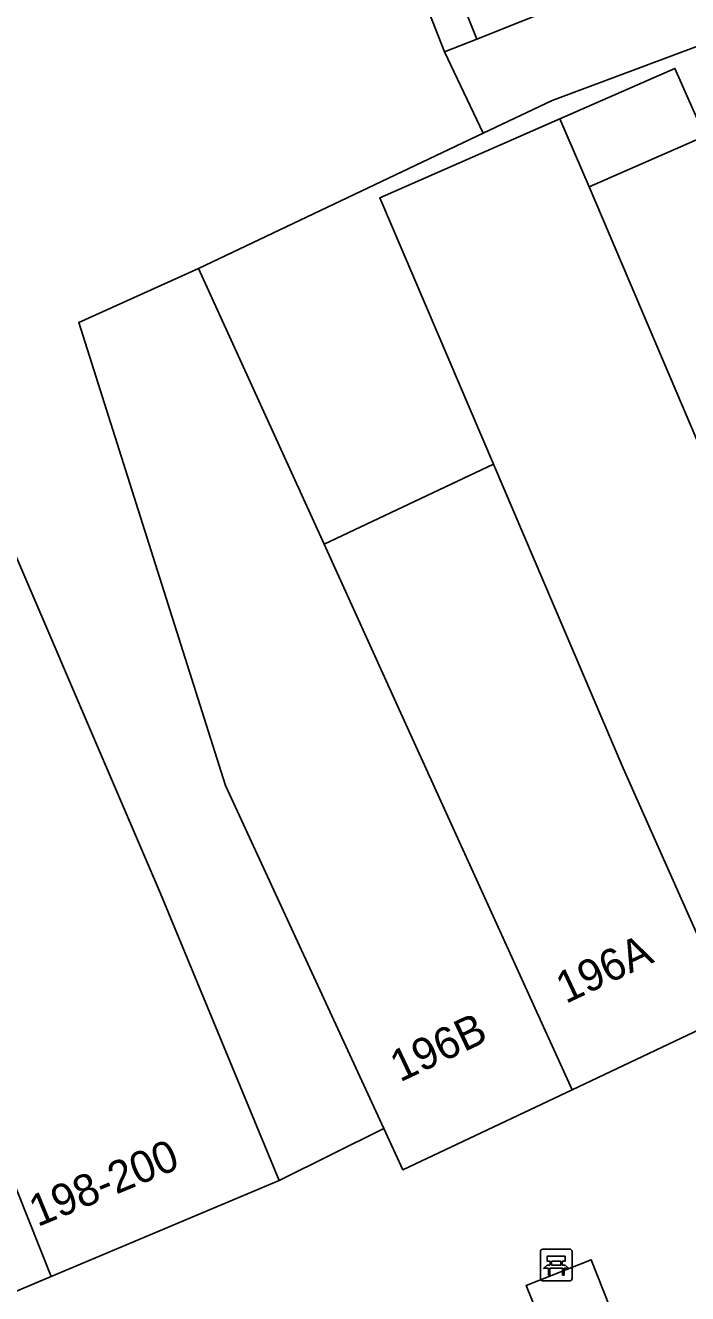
# Model space of a CAD drawing. Extents: x 159262 to 160143, y 383399 to 384319.
# Drawn here: x 159603.2 to 159624.06, y 383565.06 to 383605.01 of the extents above; entities that cross this region are included whole.
import ezdxf

# ---------------------------------------------------------------- set-up
doc = ezdxf.new("R2010")
doc.units = 0
for name, color, linetype in [('IMGEO_Bank', 7, 'Continuous'), ('IMGEO_Erf', 7, 'Continuous'), ('IMGEO_Groenvoorziening', 7, 'Continuous'), ('IMGEO_Pand', 7, 'Continuous'), ('IMGEO_Pand_nummerreeks', 7, 'Continuous'), ('IMGEO_Rijbaan_lokaal_open', 7, 'Continuous'), ('IMGEO_Voetpad_open', 7, 'Continuous')]:
    doc.layers.add(name, color=color, linetype=linetype)

msp = doc.modelspace()

# ---------------------------------------------------------------- linework, layer by layer
at = {"layer": 'IMGEO_Bank'}
for p, q in [((159619.499, 383566.463), (159620.34, 383566.463)), ((159620.34, 383566.463), (159619.499, 383566.463)), ((159619.424, 383565.538), (159619.424, 383566.379)), ((159619.424, 383566.379), (159619.424, 383565.538)), ((159619.733, 383565.969), (159619.733, 383566.075)), ((159619.777, 383566.075), (159619.777, 383565.969)), ((159620.065, 383566.081), (159619.783, 383566.081)), ((159620.071, 383565.969), (159620.071, 383566.075)), ((159620.115, 383566.075), (159620.115, 383565.969)), ((159620.424, 383566.388), (159620.424, 383565.547)), ((159620.424, 383565.547), (159620.424, 383566.388)), ((159620.121, 383565.861), (159619.728, 383565.861)), ((159619.783, 383565.963), (159620.065, 383565.963)), ((159620.349, 383565.463), (159619.508, 383565.463)), ((159619.508, 383565.463), (159620.349, 383565.463))]:
    msp.add_line(p, q, dxfattribs=at)
for points in [[(159619.727, 383566.081), (159619.641, 383566.081), (159619.641, 383566.242), (159620.204, 383566.242), (159620.204, 383566.081), (159620.121, 383566.081)], [(159619.671, 383565.861), (159619.529, 383565.861), (159619.641, 383565.963), (159619.727, 383565.963)], [(159619.721, 383565.854), (159619.721, 383565.647), (159619.678, 383565.647), (159619.678, 383565.854)], [(159620.121, 383565.963), (159620.204, 383565.963), (159620.316, 383565.861), (159620.177, 383565.861)], [(159620.171, 383565.854), (159620.171, 383565.647), (159620.127, 383565.647), (159620.127, 383565.854)]]:
    msp.add_lwpolyline(points, dxfattribs=at)
for centre, radius, start, end in [((159619.502, 383566.385), 0.0779, 92.4484, 184.2845), ((159619.502, 383566.385), 0.0779, 92.4484, 184.2845), ((159620.346, 383566.385), 0.0779, 2.4484, 94.2845), ((159620.346, 383566.385), 0.0779, 2.4484, 94.2845), ((159619.726, 383566.074), 0.00671, 2.8957, 87.1043), ((159619.783, 383566.074), 0.00671, 92.8957, 177.1043), ((159620.065, 383566.074), 0.00671, 2.8957, 87.1043), ((159620.122, 383566.074), 0.00671, 92.8957, 177.1043), ((159619.671, 383565.854), 0.00671, 2.8957, 87.1043), ((159619.728, 383565.854), 0.00671, 92.8957, 177.1043), ((159619.726, 383565.97), 0.00671, 272.8957, 357.1043), ((159619.783, 383565.97), 0.00671, 182.8957, 267.1043), ((159620.065, 383565.97), 0.00671, 272.8957, 357.1043), ((159620.122, 383565.97), 0.00671, 182.8957, 267.1043), ((159620.12, 383565.854), 0.00671, 2.8957, 87.1043), ((159620.177, 383565.854), 0.00671, 92.8957, 177.1043), ((159619.502, 383565.541), 0.0779, 182.4484, 274.2845), ((159619.502, 383565.541), 0.0779, 182.4484, 274.2845), ((159620.346, 383565.541), 0.0779, 272.4484, 4.2845), ((159620.346, 383565.541), 0.0779, 272.4484, 4.2845)]:
    msp.add_arc(centre, radius, start, end, dxfattribs=at)
at = {"layer": 'IMGEO_Erf'}
for points in [[(159613.585, 383611.396), (159616.406, 383604.171), (159617.427, 383604.579), (159616.493, 383606.914)], [(159636.572, 383608.918), (159619.795, 383602.644), (159617.623, 383601.612), (159608.659, 383597.35), (159612.61, 383588.664), (159617.946, 383591.184), (159614.365, 383599.573), (159620.042, 383602.066), (159623.663, 383603.656), (159624.602, 383601.52), (159620.958, 383599.92), (159624.537, 383591.533), (159626.924, 383592.552), (159628.221, 383589.47), (159630.076, 383585.061), (159632.865, 383586.232), (159631.239, 383590.689), (159625.697, 383604.476), (159631.459, 383606.792)]]:
    msp.add_lwpolyline(points, dxfattribs=at)
at = {"layer": 'IMGEO_Groenvoorziening'}
msp.add_lwpolyline([(159619.566, 383563.872), (159619.757, 383563.373), (159621.805, 383564.165), (159621.022, 383566.13), (159618.982, 383565.321)], close=True, dxfattribs=at)
at = {"layer": 'IMGEO_Pand'}
for points in [[(159620.937, 383608.691), (159616.493, 383606.914), (159617.427, 383604.579), (159621.871, 383606.356)], [(159620.042, 383602.066), (159620.958, 383599.92), (159624.602, 383601.52), (159623.663, 383603.656)], [(159625.844, 383588.47), (159624.537, 383591.533), (159620.958, 383599.92), (159620.042, 383602.066), (159614.365, 383599.573), (159617.946, 383591.184), (159622.03, 383581.613), (159625.472, 383573.875), (159630.844, 383576.135)], [(159620.423, 383571.487), (159614.977, 383583.46), (159612.61, 383588.664), (159608.659, 383597.35), (159604.887, 383595.655), (159609.507, 383581.069), (159614.49, 383570.268), (159615.091, 383568.965)], [(159601.127, 383592.412), (159599.929, 383595.303), (159598.584, 383594.73), (159596.38, 383593.679), (159593.336, 383592.228), (159593.928, 383590.754), (159600.778, 383573.706), (159604.021, 383565.6), (159611.199, 383568.622), (159607.455, 383577.664)], [(159620.423, 383571.487), (159625.472, 383573.875), (159622.03, 383581.613), (159617.946, 383591.184), (159612.61, 383588.664), (159614.977, 383583.46)], [(159593.928, 383590.754), (159585.134, 383587.106), (159587.556, 383582.99), (159589.785, 383583.914), (159595.01, 383571.313), (159598.106, 383564.278), (159598.54, 383563.293), (159604.021, 383565.6), (159600.778, 383573.706)]]:
    msp.add_lwpolyline(points, close=True, dxfattribs=at)
at = {"layer": 'IMGEO_Rijbaan_lokaal_open'}
msp.add_lwpolyline([(159590.113, 383612.405), (159598.584, 383594.73), (159599.929, 383595.303), (159601.127, 383592.412), (159607.455, 383577.664), (159611.199, 383568.622), (159614.49, 383570.268), (159609.507, 383581.069), (159604.887, 383595.655), (159608.659, 383597.35), (159617.623, 383601.612), (159616.406, 383604.171), (159613.585, 383611.396)], dxfattribs=at)
at = {"layer": 'IMGEO_Voetpad_open'}
msp.add_lwpolyline([(159640.104, 383611.836), (159639.671, 383612.996), (159633.561, 383610.777), (159629.243, 383609.209), (159624.48, 383607.372), (159621.871, 383606.356), (159617.427, 383604.579), (159616.406, 383604.171), (159617.623, 383601.612), (159619.795, 383602.644), (159636.572, 383608.918), (159636.048, 383610.319)], close=True, dxfattribs=at)
for points in [[(159688.804, 383595.494), (159688.204, 383597.17), (159682.426, 383595.075), (159669.157, 383590.363), (159668.084, 383589.996), (159660.005, 383587.05), (159652.491, 383584.31), (159652.199, 383584.204), (159646.946, 383582.288), (159646.566, 383582.149), (159641.364, 383580.253), (159636.253, 383578.389), (159635.861, 383578.246), (159630.844, 383576.135), (159625.472, 383573.875), (159620.423, 383571.487), (159615.091, 383568.965), (159614.49, 383570.268), (159611.199, 383568.622), (159604.021, 383565.6), (159598.54, 383563.293)], [(159572.893, 383544.474), (159573.444, 383544.691), (159572.567, 383547.038), (159583.792, 383551.383), (159584.678, 383549.036), (159590.237, 383551.186), (159589.337, 383553.529), (159613.087, 383562.722), (159613.538, 383561.556), (159619.566, 383563.872), (159618.982, 383565.321), (159621.022, 383566.13), (159621.805, 383564.165), (159619.757, 383563.373), (159620.012, 383562.705), (159622.105, 383563.501), (159626.149, 383565.073), (159625.245, 383567.397), (159643.978, 383574.584)]]:
    msp.add_lwpolyline(points, dxfattribs=at)

# ---------------------------------------------------------------- texts
at = {"layer": 'IMGEO_Pand_nummerreeks'}
for s, rotation, p in [('196A', 25.3148, (159620.226, 383574.182)), ('196B', 25.317, (159615.003, 383571.711)), ('198-200', 22.523, (159603.588, 383567.154))]:
    msp.add_text(s, height=1, rotation=rotation, dxfattribs=at).set_placement(p)

doc.saveas('drawing.dxf')
